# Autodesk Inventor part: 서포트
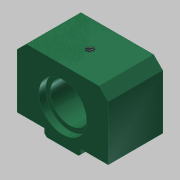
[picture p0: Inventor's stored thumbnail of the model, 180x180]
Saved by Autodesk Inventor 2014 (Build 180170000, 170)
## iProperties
Created: 2019-04
Part Number: 서포트
Material: 알루미늄 6061
Document SubType Name: Modeling
Designer: mduedu
Density: 1 g/cm^3
Appearance: 매끄러움 - 짙은 바다 녹색
Author: mduedu
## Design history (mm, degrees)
sketch "스케치1"
  geometry: L1 (3, 20)-(31, 20); L2 (31, 20)-(31, -20); L3 (31, -20)-(3, -20); L4 (0, -8)-(0, 8); L5 (0, 8)-(3, 8); L6 (3, 8)-(3, 20); L7 (0, 0)-(31, 0); L8 (0, -8)-(3, -8); L9 (3, -8)-(3, -20); 1 further point
  constraints: 18 end point, 3 symmetric about line, 2 horizontal, 2 midpoint, 2 parallel, 2 perpendicular, 1 coincident
  dimensions: "d3" = 31 distance between parallel lines of L4 L2; "d5" = 16 distance of L4.start L4.end; "d6" = 40 distance between parallel lines of L3 L1; "d7" = 3 distance between parallel lines of L4 L9
extrude "돌출1" new body sketch "스케치1" distance "d8" = 24; taper "d9" = 0 deg
chamfer "모따기1" distance "d10" = 4; stored, may be unused: second distance "d11" = 2, angle "d12" = 45 deg
chamfer "모따기2" distance "d13" = 1; stored, may be unused: second distance "d14" = 2, angle "d15" = 45 deg
sketch "스케치2"
  geometry: L1 (7, 0)-(-7, 0) reference; L2 (20, 3)-(8, 3) reference; 3 further points
  constraints: 1 midpoint, 1 vertical alignment
  dimensions: "d24" = 12 distance from line of point (0, 15) L2
hole "구멍1" sketch "스케치2" at (0, 15) diameter "d17" = 17; stored, may be unused: countersink angle "d21" = 90 deg, drill point angle "d23" = 118 deg; dims "d18" = 6, "d19" = 21, "d20" = 3, "d22" = 8
sketch "스케치3"
  geometry: L1 (0, 32)-(0, 0) reference; 3 further points
  constraints: 1 horizontal alignment, 1 midpoint
  dimensions: "d25" = 12 distance from line of point (12, 16) L1
hole "구멍2" sketch "스케치3" at (12, 16) diameter "d26" = 3.242; stored, may be unused: countersink angle "d30" = 90 deg, drill point angle "d32" = 118 deg; dims "d27" = 6, "d28" = 21, "d29" = 3, "d31" = 8
sketch "스케치4"
  geometry: L1 (0, -8)-(24, -8); L2 (24, 0.5)-(24, -16.5) reference; L3 (0, -28)-(0, -24) reference; 4 further points
  constraints: 2 end point, 2 symmetric about line, 1 horizontal, 1 horizontal alignment, 1 midpoint
  dimensions: "d33" = 6 distance from line of point (6, -22) L3; "d34" = 12 distance of point (18, -22) point (6, -22); "d35" = 28 distance of point (6, 6) point (6, -22); "d36" = 14 distance from line of point (6, -22) L1 (derived)
hole "구멍3" sketch "스케치4" at (6, -22), (18, -22), (18, 6), (6, 6) diameter "d37" = 3.242; stored, may be unused: countersink angle "d41" = 90 deg, drill point angle "d43" = 118 deg; dims "d38" = 9, "d39" = 21, "d40" = 3, "d42" = 11
node "솔리드1"
